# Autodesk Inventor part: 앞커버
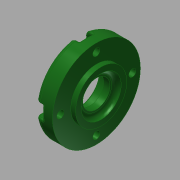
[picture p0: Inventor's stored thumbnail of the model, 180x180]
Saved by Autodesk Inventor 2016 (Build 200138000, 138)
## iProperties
Created: 2015-11
Part Number: 앞커버
Material: 알루미늄 6061
Document SubType Name: Modeling
Designer: mduedu
Density: 1 g/cm^3
Appearance: 매끄러움 - 짙은 산림 녹색
Author: mduedu
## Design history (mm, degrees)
sketch "스케치1"
  geometry: L1 (-7, 0)-(7, 0); L2 (-7, 0)-(-7, 27.5); L3 (-7, 27.5)-(4, 27.5); L4 (4, 27.5)-(4, 16); L5 (4, 16)-(7, 16); L6 (7, 16)-(7, 0); 2 further points
  constraints: 12 end point, 3 perpendicular, 2 parallel, 1 coincident, 1 horizontal, 1 midpoint
  dimensions: "d0" = 14 distance of L1.start L1.end; "d1" = 55 diameter of L3 L1; "d2" = 3 distance of L4.end L5.end; "d3" = 32 diameter of L5 L1
revolve "회전1" sketch "스케치1" stored, may be unused: angle "d4" = 90 deg
hole "구멍1" diameter "d7" = 25; stored, may be unused: countersink angle "d11" = 90 deg, drill point angle "d13" = 0 deg; dims "d5" = 10, "d6" = 10, "d8" = 6, "d9" = 4, "d10" = 2, "d12" = 3
hole "구멍2" diameter "d16" = 25; stored, may be unused: countersink angle "d20" = 90 deg, drill point angle "d22" = 0 deg; dims "d17" = 6, "d18" = 4, "d19" = 2, "d21" = 7, "d63" = 10, "d64" = 10
hole "구멍3" diameter "d25" = 17; stored, may be unused: countersink angle "d29" = 90 deg, drill point angle "d31" = 0 deg; dims "d23" = 10, "d24" = 10, "d26" = 6, "d27" = 4, "d28" = 2, "d30" = 4.2
chamfer "모따기1" distance "d32" = 0.6; stored, may be unused: second distance "d33" = 2, angle "d34" = 30 deg
fillet "모깎기1" dims "d35" = 0.3
fillet "모깎기2" dims "d36" = 3
fillet "모깎기3" dims "d37" = 3
sketch "스케치2" dims "d39" = 45
  geometry: C1 r 12.846 at (0, 0) reference; C2 r 24.5 at (0, 0) reference; 6 further points
  constraints: 2 vertical alignment, 1 coincident, 7 other
  dimensions: "d42" = 360 deg dimension on point (0, 0) point (0, 22.5) (derived)
sketch "스케치3"
  geometry: 8 further points
  constraints: 4 coincident
hole "구멍4" sketch "스케치3" at (-22.5, 0), (0, -22.5), (22.5, 0), (0, 22.5) diameter "d44" = 4.5; stored, may be unused: countersink angle "d48" = 90 deg, drill point angle "d50" = 0 deg; dims "d45" = 6, "d46" = 8, "d47" = 4.6, "d49" = 8
sketch "스케치4"
  geometry: L1 (-4, 0)-(-4, -4.708); L2 (4, 0)-(4, -4.708); A1 r 4 centre (0, 0) between (-4, 0) and (4, 0) reference; A2 r 27.5 centre (0, 22.5) between (-4, -4.708) and (4, -4.708) reference; 3 further points
  constraints: 4 end point, 4 point on circle, 2 tangent, 1 parallel, 1 vertical
extrude "돌출1" cut sketch "스케치4" stored distance "d51" = 0; taper "d52" = 0 deg
fillet "모깎기5" dims "d56" = 0.3
fillet "모깎기6" dims "d57" = 1
node "솔리드1"
pattern_circular "원형 패턴1" dims angle "d54" = 360 deg
